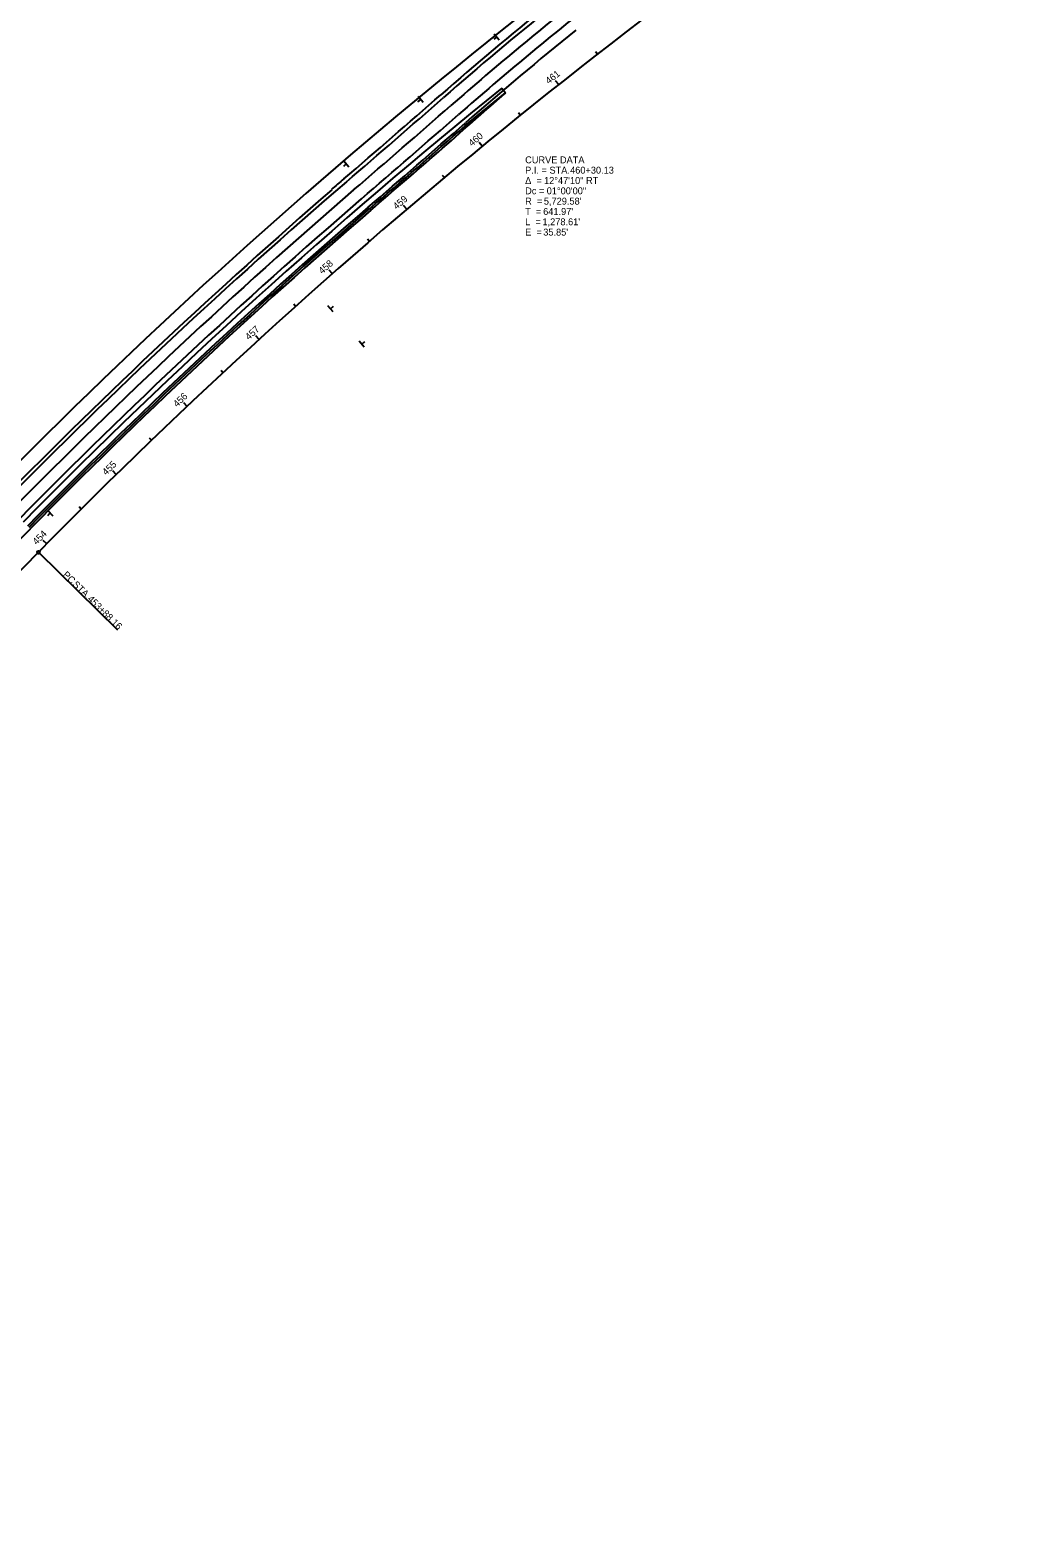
# Model space of a CAD drawing. Extents: x 142554 to 147512, y 370190 to 373751.
# Drawn here: x 145352 to 146350, y 371103 to 372636 of the extents above; entities that cross this region are included whole.
import ezdxf

# ---------------------------------------------------------------- set-up
doc = ezdxf.new("R2010")
doc.units = 0
for name, color, linetype in [('DR_P_Cells', 7, 'Continuous'), ('DR_X_GenericNode', 7, 'Continuous'), ('FeatureService_Stream Network', 7, 'Continuous'), ('FeatureService_Water Bodies', 7, 'Continuous'), ('PF_X_Ground_Line', 7, 'Continuous'), ('PM_X_Channelizing_Line', 7, 'Continuous'), ('PM_X_Edge_Line', 7, 'Continuous'), ('PM_X_Transverse_Line', 7, 'Continuous'), ('RD_X_GR_Cable_Bar', 7, 'Continuous'), ('RD_X_GR_Lt', 7, 'Continuous'), ('SC_Scratch20', 7, 'Continuous')]:
    doc.layers.add(name, color=color, linetype=linetype)

msp = doc.modelspace()

# ---------------------------------------------------------------- linework, layer by layer
at = {"layer": 'DR_P_Cells'}
for centre, radius, start, end in [((148078, 369935.4), 3488, 128.1463, 131.2155), ((148078, 369935.4), 3476, 128.1473, 131.2155), ((135888.5, 383851.8), 15012, 310.71653, 311.21549), ((135888.5, 383851.8), 15024, 310.71653, 311.21549), ((149413.6, 368136.5), 5722, 130.7165, 135.4923), ((149413.6, 368136.5), 5710, 130.7165, 135.4923)]:
    msp.add_arc(centre, radius, start, end, dxfattribs=at)
at = {"layer": 'DR_X_GenericNode'}
for centre, radius, start, end in [((148078.6, 369934.6), 3500, 126.5154, 131.2155), ((148077.2, 369936), 3464, 128.7913, 131.2155), ((135889.1, 383851), 15000, 310.71653, 311.21549), ((135887.7, 383852.4), 15036, 310.71653, 311.21549), ((149414.2, 368135.8), 5734, 130.71653, 135.49226), ((149412.8, 368137.2), 5698, 130.7165, 135.4923)]:
    msp.add_arc(centre, radius, start, end, dxfattribs=at)
at = {"layer": 'FeatureService_Stream Network'}
for centre, radius, start, end in [((148077.2, 369936), 3502, 126.6251, 131.2155), ((135887.7, 383852.4), 14998, 310.71653, 311.21549), ((149412.8, 368137.2), 5735.5, 130.88395, 135.49226), ((149412.8, 368137.2), 5736, 130.71653, 130.884)]:
    msp.add_arc(centre, radius, start, end, dxfattribs=at)
at = {"layer": 'FeatureService_Water Bodies'}
msp.add_line((145794.3, 372538.7), (145835.6, 372572.3), dxfattribs=at)
msp.add_line((145794.3, 372538.7), (145835.6, 372572.3), dxfattribs=at)
msp.add_lwpolyline([(145352.1, 372128.7), (145150.9, 371924), (144951.3, 371715.9), (144938.2, 371702.6), (144671.6, 371431.1), (144394, 371160.2)], dxfattribs=at)
msp.add_lwpolyline([(145352.1, 372128.7), (145150.9, 371924), (144951.3, 371715.9), (144938.2, 371702.6), (144671.6, 371431.1), (144394, 371160.2)], dxfattribs=at)
for centre, radius, start, end in [((135887.7, 383852.4), 15040, 310.71653, 311.40914), ((135887.7, 383852.4), 15040, 310.71653, 311.40914), ((135887.7, 383852.4), 15038, 310.71653, 311.20635), ((135887.7, 383852.4), 15038, 310.71653, 311.20635), ((149412.8, 368137.2), 5696, 130.7165, 135.4923), ((149412.8, 368137.2), 5696, 130.7165, 135.4923), ((149412.8, 368137.2), 5694, 130.7165, 135.4923), ((149412.8, 368137.2), 5694, 130.7165, 135.4923)]:
    msp.add_arc(centre, radius, start, end, dxfattribs=at)
at = {"layer": 'PF_X_Ground_Line'}
for p, q in [((145835.6, 372572.3), (145794.3, 372538.7)), ((145831.8, 372577), (145835.6, 372572.3))]:
    msp.add_line(p, q, dxfattribs=at)
for centre, radius, start, end in [((149412.8, 368137.2), 5704, 128.8881, 135.4923), ((135887.7, 383852.4), 15038, 310.71653, 311.20635), ((149412.8, 368137.2), 5696, 130.7165, 135.4923)]:
    msp.add_arc(centre, radius, start, end, dxfattribs=at)
at = {"layer": 'PM_X_Channelizing_Line'}
msp.add_line((145360.6, 372105.1), (145440.8, 372026.2), dxfattribs=at)
msp.add_circle((145360.6, 372105.1), 1.5, dxfattribs=at)
at = {"layer": 'PM_X_Edge_Line'}
msp.add_line((144376.2, 371102.8), (145360.6, 372105.1), dxfattribs=at)
msp.add_arc((149448.4, 368090.4), 5729.6, 122.7308, 135.5169, dxfattribs=at)
msp.add_arc((149448.4, 368090.4), 5729.6, 122.7308, 135.5169, dxfattribs=at)
at = {"layer": 'RD_X_GR_Cable_Bar'}
for p, q in [((145928.9, 372611.6), (145927.1, 372613.9)), ((145889.6, 372580.7), (145886.5, 372584.6)), ((145850.5, 372549.5), (145848.6, 372551.8)), ((145811.8, 372517.9), (145808.6, 372521.8)), ((145773.3, 372486), (145771.3, 372488.3)), ((145735, 372453.8), (145731.8, 372457.6)), ((145697.1, 372421.2), (145695.1, 372423.4)), ((145659.5, 372388.3), (145656.1, 372392)), ((145622.1, 372355.1), (145620.1, 372357.3)), ((145585, 372321.5), (145581.6, 372325.2)), ((145548.2, 372287.6), (145546.2, 372289.8)), ((145511.8, 372253.4), (145508.3, 372257.1)), ((145475.6, 372218.9), (145473.5, 372221.1)), ((145439.7, 372184.1), (145436.2, 372187.7)), ((145404.1, 372149), (145402, 372151.1)), ((145368.9, 372113.5), (145365.3, 372117))]:
    msp.add_line(p, q, dxfattribs=at)
at = {"layer": 'RD_X_GR_Lt'}
for p, q in [((145826.6, 372629.3), (145823.5, 372626.8)), ((145824.1, 372632.4), (145829.2, 372626.2)), ((145826.6, 372629.3), (145826.6, 372629.3)), ((145749.1, 372565.6), (145746.1, 372563.1)), ((145746.6, 372568.7), (145751.7, 372562.6)), ((145749.1, 372565.6), (145749.1, 372565.6)), ((145671, 372503.1), (145676.3, 372497.1)), ((145673.6, 372500.1), (145670.6, 372497.5)), ((145673.6, 372500.1), (145673.6, 372500.1)), ((145660.1, 372349.6), (145654.8, 372355.6)), ((145657.4, 372352.6), (145660.5, 372355.2)), ((145657.4, 372352.6), (145657.4, 372352.6)), ((145691.9, 372313.7), (145686.7, 372319.7)), ((145689.3, 372316.7), (145692.3, 372319.3)), ((145689.3, 372316.7), (145689.3, 372316.7)), ((145369.6, 372147.8), (145375.3, 372142.2)), ((145372.5, 372145), (145369.6, 372142.2)), ((145372.4, 372145), (145372.4, 372145))]:
    msp.add_line(p, q, dxfattribs=at)
at = {"layer": 'SC_Scratch20'}
msp.add_arc((149412.8, 368137.2), 5750, 122.73083, 135.49226, dxfattribs=at)

# ---------------------------------------------------------------- texts
at = {"layer": 'PM_X_Channelizing_Line'}
for s, p in [('PC', (145384.7, 372081.5)), (' STA. ', (145392.9, 372073.5)), ('453+88.16', (145409.8, 372056.9))]:
    msp.add_text(s, height=7, rotation=315.5169, dxfattribs=at).set_placement(p)
at = {"layer": 'PM_X_Transverse_Line'}
for s, p in [('CURVE DATA', (145855.5, 372500.6)), ('Δ  = ', (145855.5, 372479.6)), ('P.I. = STA. ', (145855.5, 372490.1)), ('12°47\'10" RT', (145874.7, 372479.6)), ('460+30.13', (145901.2, 372490.1)), ('Dc = ', (145855.5, 372469.1)), ('01°00\'00"', (145877.4, 372469.1)), ('T  = ', (145855.5, 372448.1)), ('R  = ', (145855.5, 372458.6)), ("641.97'", (145873.8, 372448.1)), ("5,729.58'", (145874.5, 372458.6)), ('L  = ', (145855.5, 372437.6)), ("1,278.61'", (145873.1, 372437.6)), ('E  = ', (145855.5, 372427.1)), ("35.85'", (145873.9, 372427.1))]:
    msp.add_text(s, height=7, dxfattribs=at).set_placement(p)
at = {"layer": 'RD_X_GR_Cable_Bar'}
for s, rotation, p in [('461', 38.3985, (145879.5, 372580.7)), ('460', 39.3985, (145801.3, 372517.4)), ('459', 40.3985, (145724.7, 372453.1)), ('458', 41.3985, (145649.1, 372387.5)), ('457', 42.3985, (145574.5, 372320.4)), ('456', 43.3985, (145501.4, 372252.2)), ('455', 44.3985, (145429.4, 372182.8)), ('454', 45.3985, (145358.7, 372112.1))]:
    msp.add_text(s, height=7, rotation=rotation, dxfattribs=at).set_placement(p)

doc.saveas('drawing.dxf')
